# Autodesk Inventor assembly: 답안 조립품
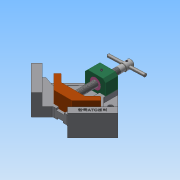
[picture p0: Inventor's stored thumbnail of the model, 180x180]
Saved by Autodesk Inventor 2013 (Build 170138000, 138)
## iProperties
Created: 2019-04
Part Number: 답안 조립품
Document SubType Name: Assembly
Designer: Administrator
Author: Administrator
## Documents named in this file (11)
- C:\Users\Administrator\Desktop\490407V1032\답안 조립품.iam
- C:\Users\Administrator\Desktop\490407V1032\본체.ipt
- C:\Users\Administrator\Desktop\490407V1032\볼트 M4x16.ipt
- C:\Users\Administrator\Desktop\490407V1032\서포트.ipt
- C:\Users\Administrator\Desktop\490407V1032\리드스크류.ipt
- C:\Users\Administrator\Desktop\490407V1032\멈춤나사 M4x5.ipt
- C:\Users\Administrator\Desktop\490407V1032\핸들.ipt
- C:\Users\Administrator\Desktop\490407V1032\부시.ipt
- C:\Users\Administrator\Desktop\490407V1032\멈춤나사 M4x10.ipt
- C:\Users\Administrator\Desktop\490407V1032\조.ipt
- C:\Users\Administrator\Desktop\490407V1032\평행 핀 2.5x24.ipt
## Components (1 placed, 1 different names)
1. 핸들:1
